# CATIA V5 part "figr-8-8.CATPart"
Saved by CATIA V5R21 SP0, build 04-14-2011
Part number: Part1
Bounding box of the stored display mesh (mm): x 4.549 to 89.781, y -52.238 to 26.36, z 54 to 147.773
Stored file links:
  D:\CATIA V5R21 E-RESOURCES\CATIA-V5R21\catia-v5r21-prt\c08-catia-v5r20-prt\c08-catia-v5r21-figr-8-8.CATPart
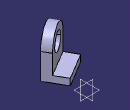
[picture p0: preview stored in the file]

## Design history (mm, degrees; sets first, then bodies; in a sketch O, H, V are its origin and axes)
Body1 (main body)
  Sketch1 on yz-plane, origin (0, 0, 0), H (0, 1, 0), V (0, 0, 1)
    point P1 (-104.4861, 0)
    line L1 (-104.4861, 0) -> (-104.4861, 44.267)
    arc A1 centre (-69.7903, 44.267) radius 34.6958 from (-104.4861, 44.267) to (-35.0946, 44.267) cw
    line L2 (-35.0946, 44.267) -> (-35.0946, 0)
    point P5 (-35.0946, 0)
    line L3 (-35.0946, 0) -> (-104.4861, 0)
    circle A2 centre (-69.7903, 44.267) radius 19.5413
    coincidence: P1 H, P5 H
    vertical: L1 V
    tangency: A1 L1, L2 A1
    horizontal: L3 H
  Pad1: profile Sketch1, direction (1, 0, 0), length 20
  Sketch2 on face of Pad1, origin (0, 0, 0), H (0, -1, 0), V (0, 0, 1)
    point P1 (35.0946, 0)
    line L1 (35.0946, 0) -> (104.4861, 0)
    line L2 (104.4861, 0) -> (104.4861, -15)
    line L3 (104.4861, -15) -> (35.0946, -15)
    line L4 (35.0946, -15) -> (35.0946, 0)
    reference projected line E1 (35.0946, 0) -> (35.0946, 44.267) from edge [face of Pad1 | face of Pad1]
    reference projected line E2 (104.4861, 44.267) -> (104.4861, 0) from edge [face of Pad1 | face of Pad1]
    distance L3 L1 = 15
    coincidence: P1 H, L4 E1, L2 E2
    horizontal: L1 H, L3 H
    vertical: L2 V, L4 V
  Pad2: profile Sketch2, direction (1, 0, 0), length 50
  Translate1: ToTransfor Pad2, Direction xy-plane, Length 69
  Rotate1: ToTransfor Translate1, Axis edge, Angle 121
